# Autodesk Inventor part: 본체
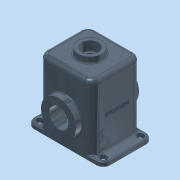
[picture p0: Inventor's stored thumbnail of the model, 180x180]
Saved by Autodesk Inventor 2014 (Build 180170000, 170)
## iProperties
Company: 한국ATC센터
Created: 2014-10
Part Number: 본체
Document SubType Name: Modeling
Designer: 한국ATC센터
Density: 2.71 g/cm^3
Material: 알루미늄 6061
Mass: 3285.44 g
Surface Area: 2358.48 cm^2
Volume: 1212.34 cm^3
Appearance: 청회색(진함/광택)
Author: KYOUNG IL JANG
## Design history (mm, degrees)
sketch "스케치1"
  geometry: L1 (-70, 65)-(70, 65); L2 (70, 65)-(70, -65); L3 (70, -65)-(-70, -65); L4 (-70, -65)-(-70, 65); 3 further points
  constraints: 8 end point, 2 midpoint, 2 parallel, 1 horizontal, 1 horizontal alignment, 1 perpendicular, 1 vertical alignment
  dimensions: "d0" = 140 distance of L2.end L3.end; "d68" = 130 distance of L3.end L1.start
extrude "돌출1" new body sketch "스케치1" distance "d1" = 180; taper "d2" = 0 deg
fillet "모깎기1" dims "d3" = 20
feature "쉘1" dims "d4" = 10
sketch "스케치2"
  geometry: L1 (-70, 45)-(-70, -45) reference; L2 (-50, -65)-(-82, -65); L3 (-82, 65)-(-50, 65); L4 (-85, 57)-(-82, 57); L5 (-82, 41)-(-85, 41); L6 (-100, 47)-(-100, -47); A1 r 20 centre (-50, 45) between (-50, 65) and (-70, 45) reference; A2 r 20 centre (-50, -45) between (-70, -45) and (-50, -65) reference; A3 r 8 centre (-82, 49) between (-82, 41) and (-82, 57); A4 r 8 centre (-85, 49) between (-85, 57) and (-85, 41); A5 r 18 centre (-82, 47) between (-82, 65) and (-100, 47); A6 r 18 centre (-82, -47) between (-100, -47) and (-82, -65); 1 further point
  constraints: 10 end point, 9 tangent, 8 point on circle, 4 centre point, 2 parallel, 2 perpendicular, 1 equal radius
  dimensions: "d6" = 49 vertical distance of point (0, 0) A3.centre; "d8" = 16 distance between parallel lines of L4 L5; "d64" = 18 radius of A5; "d65" = 12 distance from line of A3.centre L1; "d66" = 30 distance between parallel lines of L6 L1; "d67" = 3 distance of A4.centre A3.centre
extrude "돌출2" join sketch "스케치2" distance "d9" = 10; taper "d10" = 0 deg
extrude "돌출3" cut sketch "스케치2" stored distance "d11" = 10; taper "d12" = 0 deg
sketch "스케치3"
  geometry: L1 (-65, 0)-(-65, 180) reference; L2 (-55, 0)-(-55, 170) reference; L3 (-83, 75)-(-51, 75); L4 (45, 0)-(-45, 0) reference; L5 (-83, 75)-(-83, 120.5); L6 (-83, 120.5)-(-55, 120.5); L7 (-55, 120.5)-(-51, 116.5); L8 (-51, 116.5)-(-51, 75); 2 further points
  constraints: 10 end point, 4 perpendicular, 1 point on line
  dimensions: "d13" = 75 distance between parallel lines of L3 L4; "d14" = 18 distance from line of L1 L3.start; "d15" = 4 distance from line of L3.end L2; "d16" = 91 diameter of L6 L3; "d17" = 135 deg angle of L7 L2
revolve "회전1" sketch "스케치3" stored, may be unused: angle "d18" = 90 deg
sketch "스케치4"
  geometry: C1 r 45.5 at (0, 0) reference; 2 further points
  constraints: 1 vertical alignment
  dimensions: "d19" = 35 distance of C1.centre point (0, 35)
hole "구멍1" sketch "스케치4" at (0, 35) diameter "d20" = 3.459; stored, may be unused: countersink angle "d24" = 90 deg, drill point angle "d26" = 118 deg; dims "d21" = 13, "d22" = 4, "d23" = 2, "d25" = 16
fillet "모깎기2" dims "d30" = 3
hole "구멍2" diameter "d33" = 52; stored, may be unused: countersink angle "d37" = 90 deg, drill point angle "d39" = 118 deg; dims "d31" = 10, "d32" = 10, "d34" = 13, "d35" = 4, "d36" = 2, "d38" = 16
sketch "스케치5"
  geometry: C1 r 31 at (0, 0); 1 further point
  constraints: 1 centre point, 1 coincident
  dimensions: "d40" = 62 diameter of C1
extrude "돌출4" join sketch "스케치5" distance "d41" = 15; taper "d42" = 0 deg
hole "구멍3" diameter "d45" = 43; stored, may be unused: countersink angle "d49" = 90 deg, drill point angle "d51" = 118 deg; dims "d43" = 10, "d44" = 10, "d46" = 13, "d47" = 4, "d48" = 2, "d50" = 16
fillet "모깎기3" dims "d52" = 3
fillet "모깎기4" dims "d53" = 3
chamfer "모따기1" distance "d55" = 1; stored, may be unused: second distance "d56" = 2, angle "d57" = 45 deg
sketch "스케치6"
  geometry: 2 further points
  constraints: 1 vertical alignment, 1 other
  dimensions: "d71" = 90 distance of point (0, 0) point (0, 90)
feature "엠보싱2" sketch "스케치6" dims "d0" = 140, "d68" = 130, "d72" = 1, "d73" = 0
fillet "모깎기6" dims "d74" = 10
sketch "스케치7"
  geometry: C1 r 15 at (0, 0); C2 r 21.5 at (0, 0) reference; C3 r 25 at (0, 0); 1 further point
  constraints: 2 centre point, 2 coincident
  dimensions: "d61" = 30 diameter of C1; "d75" = 50 diameter of C3
extrude "돌출5" join sketch "스케치7" distance "d62" = 10; taper "d63" = 0 deg
feature "면 이동1" dims "d76" = 1
fillet "모깎기7" dims "d77" = 3
node "솔리드1"
mirror "대칭1"
mirror "대칭2"
pattern_circular "원형 패턴1" dims angle "d28" = 360 deg
mirror "대칭3"
